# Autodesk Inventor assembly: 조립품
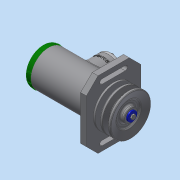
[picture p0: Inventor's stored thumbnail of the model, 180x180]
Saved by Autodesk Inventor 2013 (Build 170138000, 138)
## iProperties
Created: 2017-10
Part Number: 조립품
Document SubType Name: Assembly
Designer: dgall
Author: dgall
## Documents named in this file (20)
- C:\Users\dgall\Desktop\471007V1016\조립품.iam
- C:\Users\dgall\Desktop\471007V1016\본체.ipt
- C:\Users\dgall\Desktop\471007V1016\축.ipt
- C:\Users\dgall\Desktop\471007V1016\베어링 15 x 35 x 11.ipt
- C:\Users\dgall\Desktop\471007V1016\멈춤링 15 x 1.ipt
- C:\Users\dgall\Desktop\471007V1016\멈춤링 35x1.6.ipt
- C:\Users\dgall\Desktop\471007V1016\부시1.ipt
- C:\Users\dgall\Desktop\471007V1016\너트 M10.ipt
- C:\Users\dgall\Desktop\471007V1016\부시2.ipt
- C:\Users\dgall\Desktop\471007V1016\와셔 10x21.ipt
- C:\Users\dgall\Desktop\471007V1016\사이드 커버.ipt
- 사이드 커버.ipt
- C:\Users\dgall\Desktop\471007V1016\탑 커버.ipt
- C:\Users\dgall\Desktop\471007V1016\십자볼트 M3 x 10.ipt
- C:\Users\dgall\Desktop\471007V1016\와셔 3x6.ipt
- C:\Users\dgall\Desktop\471007V1016\오일 실 15 25 7.ipt
- C:\Users\dgall\Desktop\471007V1016\키 4 x 4 x 18.ipt
- C:\Users\dgall\Desktop\471007V1016\V-벨트풀리.ipt
- C:\Users\dgall\Desktop\471007V1016\볼트 M4 x 10.ipt
- C:\Users\dgall\Desktop\471007V1016\와셔 4x16.ipt
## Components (2 placed, 2 different names)
1. V-벨트풀리:1
2. ISO 4017 M4 x 10:1
